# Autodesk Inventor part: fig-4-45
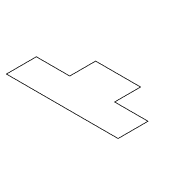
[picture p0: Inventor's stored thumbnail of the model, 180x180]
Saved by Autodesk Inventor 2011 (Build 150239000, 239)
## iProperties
Created: 2004-05
Part Number: fig-4-45
Document SubType Name: Modeling
Designer: CADCIM Technologies
Manufacturer: Standard
Standards Organization: Custom
Density: 1 g/cm^3
Author: CADCIM Technologies
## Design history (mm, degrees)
sketch "Sketch1"
  geometry: L1 (31.783, 34.561)-(31.783, 22.933); L2 (31.783, 22.933)-(16.796, 22.933); L3 (16.796, 22.933)-(16.796, 9.496); L4 (16.796, 9.496)-(66.925, 9.496); L5 (66.925, 9.496)-(66.925, 22.933); L6 (66.925, 22.933)-(51.938, 22.933); L7 (51.938, 22.933)-(51.938, 34.561); L8 (51.938, 34.561)-(31.783, 34.561)
  constraints: 16 end point, 5 parallel, 2 equal length, 1 collinear, 1 perpendicular, 1 vertical, 1 other
